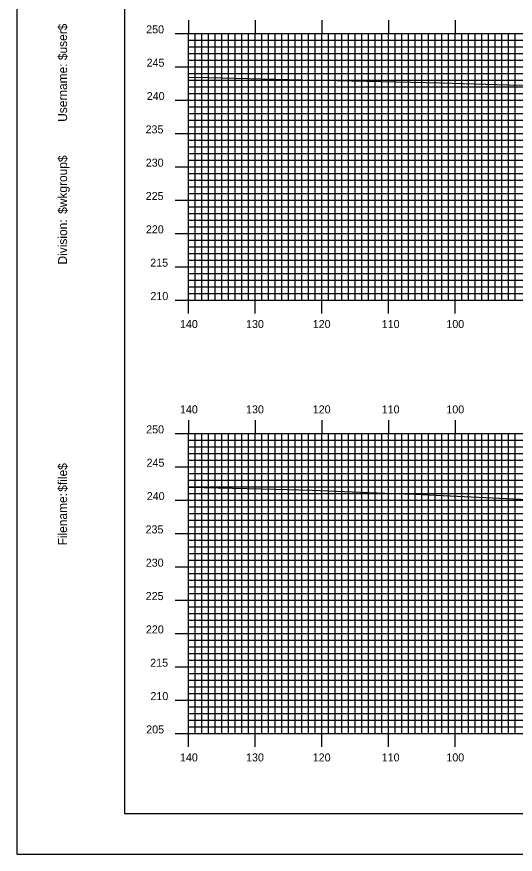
# Model space of a CAD drawing. Extents: x 1816489 to 1816833, y 442591 to 442811.
# Drawn here: x 1816489.3 to 1816564.1, y 442590.5 to 442716.2 of the extents above; entities that cross this region are included whole.
import ezdxf

# ---------------------------------------------------------------- set-up
doc = ezdxf.new("R2010")
doc.units = 0
for name, color, linetype in [('BORDER', 7, 'Continuous'), ('H_V ANNOTATION', 7, 'Continuous'), ('MAJOR', 7, 'Continuous'), ('MINOR', 7, 'Continuous'), ('PLOT BOUNDARY', 7, 'Continuous'), ('S_Roadway_Centerline', 7, 'Continuous')]:
    doc.layers.add(name, color=color, linetype=linetype)

msp = doc.modelspace()

# ---------------------------------------------------------------- linework, layer by layer
at = {"layer": 'BORDER'}
msp.add_lwpolyline([(1816505.47, 442596.67), (1816825.47, 442596.67), (1816825.47, 442806.67), (1816505.47, 442806.67)], close=True, dxfattribs=at)
at = {"layer": 'MAJOR'}
for p, q in [((1816515.07, 442715.67), (1816515.07, 442713.67)), ((1816525.07, 442715.67), (1816525.07, 442713.67)), ((1816535.07, 442715.67), (1816535.07, 442713.67)), ((1816545.07, 442715.67), (1816545.07, 442713.67)), ((1816555.07, 442715.67), (1816555.07, 442713.67)), ((1816513.07, 442713.67), (1816515.07, 442713.67)), ((1816515.07, 442713.67), (1816795.07, 442713.67)), ((1816515.07, 442673.67), (1816515.07, 442713.67)), ((1816515.07, 442673.67), (1816515.07, 442713.67)), ((1816515.07, 442713.67), (1816795.07, 442713.67)), ((1816525.07, 442673.67), (1816525.07, 442713.67)), ((1816535.07, 442673.67), (1816535.07, 442713.67)), ((1816545.07, 442673.67), (1816545.07, 442713.67)), ((1816555.07, 442673.67), (1816555.07, 442713.67)), ((1816513.07, 442708.67), (1816515.07, 442708.67)), ((1816515.07, 442708.67), (1816795.07, 442708.67)), ((1816513.07, 442703.67), (1816515.07, 442703.67)), ((1816515.07, 442703.67), (1816795.07, 442703.67)), ((1816513.07, 442698.67), (1816515.07, 442698.67)), ((1816515.07, 442698.67), (1816795.07, 442698.67)), ((1816513.07, 442693.67), (1816515.07, 442693.67)), ((1816515.07, 442693.67), (1816795.07, 442693.67)), ((1816513.07, 442688.67), (1816515.07, 442688.67)), ((1816515.07, 442688.67), (1816795.07, 442688.67)), ((1816513.07, 442683.67), (1816515.07, 442683.67)), ((1816515.07, 442683.67), (1816795.07, 442683.67)), ((1816513.07, 442678.67), (1816515.07, 442678.67)), ((1816515.07, 442678.67), (1816795.07, 442678.67)), ((1816513.07, 442673.67), (1816515.07, 442673.67)), ((1816515.07, 442673.67), (1816795.07, 442673.67)), ((1816515.07, 442673.67), (1816795.07, 442673.67)), ((1816515.07, 442671.66), (1816515.07, 442673.67)), ((1816525.07, 442671.66), (1816525.07, 442673.67)), ((1816535.07, 442671.66), (1816535.07, 442673.67)), ((1816545.07, 442671.66), (1816545.07, 442673.67)), ((1816555.07, 442671.66), (1816555.07, 442673.67)), ((1816515.07, 442655.67), (1816515.07, 442653.67)), ((1816525.07, 442655.67), (1816525.07, 442653.67)), ((1816535.07, 442655.67), (1816535.07, 442653.67)), ((1816545.07, 442655.67), (1816545.07, 442653.67)), ((1816555.07, 442655.67), (1816555.07, 442653.67)), ((1816513.07, 442653.67), (1816515.07, 442653.67)), ((1816515.07, 442653.67), (1816795.07, 442653.67)), ((1816515.07, 442608.67), (1816515.07, 442653.67)), ((1816515.07, 442608.67), (1816515.07, 442653.67)), ((1816515.07, 442653.67), (1816795.07, 442653.67)), ((1816525.07, 442608.67), (1816525.07, 442653.67)), ((1816535.07, 442608.67), (1816535.07, 442653.67)), ((1816545.07, 442608.67), (1816545.07, 442653.67)), ((1816555.07, 442608.67), (1816555.07, 442653.67)), ((1816513.07, 442648.67), (1816515.07, 442648.67)), ((1816515.07, 442648.67), (1816795.07, 442648.67)), ((1816513.07, 442643.67), (1816515.07, 442643.67)), ((1816515.07, 442643.67), (1816795.07, 442643.67)), ((1816513.07, 442638.67), (1816515.07, 442638.67)), ((1816515.07, 442638.67), (1816795.07, 442638.67)), ((1816513.07, 442633.67), (1816515.07, 442633.67)), ((1816515.07, 442633.67), (1816795.07, 442633.67)), ((1816513.07, 442628.67), (1816515.07, 442628.67)), ((1816515.07, 442628.67), (1816795.07, 442628.67)), ((1816513.07, 442623.67), (1816515.07, 442623.67)), ((1816515.07, 442623.67), (1816795.07, 442623.67)), ((1816513.07, 442618.67), (1816515.07, 442618.67)), ((1816515.07, 442618.67), (1816795.07, 442618.67)), ((1816513.07, 442613.67), (1816515.07, 442613.67)), ((1816515.07, 442613.67), (1816795.07, 442613.67)), ((1816513.07, 442608.67), (1816515.07, 442608.67)), ((1816515.07, 442608.67), (1816795.07, 442608.67)), ((1816515.07, 442608.67), (1816795.07, 442608.67)), ((1816515.07, 442606.66), (1816515.07, 442608.67)), ((1816525.07, 442606.66), (1816525.07, 442608.67)), ((1816535.07, 442606.66), (1816535.07, 442608.67)), ((1816545.07, 442606.66), (1816545.07, 442608.67)), ((1816555.07, 442606.66), (1816555.07, 442608.67))]:
    msp.add_line(p, q, dxfattribs=at)
at = {"layer": 'MINOR'}
for p, q in [((1816516.07, 442673.67), (1816516.07, 442713.67)), ((1816517.07, 442673.67), (1816517.07, 442713.67)), ((1816518.07, 442673.67), (1816518.07, 442713.67)), ((1816519.07, 442673.67), (1816519.07, 442713.67)), ((1816520.07, 442673.67), (1816520.07, 442713.67)), ((1816521.07, 442673.67), (1816521.07, 442713.67)), ((1816522.07, 442673.67), (1816522.07, 442713.67)), ((1816523.07, 442673.67), (1816523.07, 442713.67)), ((1816524.07, 442673.67), (1816524.07, 442713.67)), ((1816526.07, 442673.67), (1816526.07, 442713.67)), ((1816527.07, 442673.67), (1816527.07, 442713.67)), ((1816528.07, 442673.67), (1816528.07, 442713.67)), ((1816529.07, 442673.67), (1816529.07, 442713.67)), ((1816530.07, 442673.67), (1816530.07, 442713.67)), ((1816531.07, 442673.67), (1816531.07, 442713.67)), ((1816532.07, 442673.67), (1816532.07, 442713.67)), ((1816533.07, 442673.67), (1816533.07, 442713.67)), ((1816534.07, 442673.67), (1816534.07, 442713.67)), ((1816536.07, 442673.67), (1816536.07, 442713.67)), ((1816537.07, 442673.67), (1816537.07, 442713.67)), ((1816538.07, 442673.67), (1816538.07, 442713.67)), ((1816539.07, 442673.67), (1816539.07, 442713.67)), ((1816540.07, 442673.67), (1816540.07, 442713.67)), ((1816541.07, 442673.67), (1816541.07, 442713.67)), ((1816542.07, 442673.67), (1816542.07, 442713.67)), ((1816543.07, 442673.67), (1816543.07, 442713.67)), ((1816544.07, 442673.67), (1816544.07, 442713.67)), ((1816546.07, 442673.67), (1816546.07, 442713.67)), ((1816547.07, 442673.67), (1816547.07, 442713.67)), ((1816548.07, 442673.67), (1816548.07, 442713.67)), ((1816549.07, 442673.67), (1816549.07, 442713.67)), ((1816550.07, 442673.67), (1816550.07, 442713.67)), ((1816551.07, 442673.67), (1816551.07, 442713.67)), ((1816552.07, 442673.67), (1816552.07, 442713.67)), ((1816553.07, 442673.67), (1816553.07, 442713.67)), ((1816554.07, 442673.67), (1816554.07, 442713.67)), ((1816556.07, 442673.67), (1816556.07, 442713.67)), ((1816557.07, 442673.67), (1816557.07, 442713.67)), ((1816558.07, 442673.67), (1816558.07, 442713.67)), ((1816559.07, 442673.67), (1816559.07, 442713.67)), ((1816560.07, 442673.67), (1816560.07, 442713.67)), ((1816561.07, 442673.67), (1816561.07, 442713.67)), ((1816562.07, 442673.67), (1816562.07, 442713.67)), ((1816563.07, 442673.67), (1816563.07, 442713.67)), ((1816564.07, 442673.67), (1816564.07, 442713.67)), ((1816515.07, 442712.67), (1816795.07, 442712.67)), ((1816515.07, 442712.67), (1816517.08, 442712.67)), ((1816515.07, 442711.67), (1816795.07, 442711.67)), ((1816515.07, 442711.67), (1816517.08, 442711.67)), ((1816515.07, 442710.67), (1816795.07, 442710.67)), ((1816515.07, 442710.67), (1816517.08, 442710.67)), ((1816515.07, 442709.67), (1816795.07, 442709.67)), ((1816515.07, 442709.67), (1816517.08, 442709.67)), ((1816515.07, 442707.67), (1816795.07, 442707.67)), ((1816515.07, 442707.67), (1816517.08, 442707.67)), ((1816515.07, 442706.67), (1816795.07, 442706.67)), ((1816515.07, 442706.67), (1816517.08, 442706.67)), ((1816515.07, 442705.67), (1816795.07, 442705.67)), ((1816515.07, 442705.67), (1816517.08, 442705.67)), ((1816515.07, 442704.67), (1816795.07, 442704.67)), ((1816515.07, 442704.67), (1816517.08, 442704.67)), ((1816515.07, 442702.67), (1816795.07, 442702.67)), ((1816515.07, 442702.67), (1816517.08, 442702.67)), ((1816515.07, 442701.67), (1816795.07, 442701.67)), ((1816515.07, 442701.67), (1816517.08, 442701.67)), ((1816515.07, 442700.67), (1816795.07, 442700.67)), ((1816515.07, 442700.67), (1816517.08, 442700.67)), ((1816515.07, 442699.67), (1816795.07, 442699.67)), ((1816515.07, 442699.67), (1816517.08, 442699.67)), ((1816515.07, 442697.67), (1816795.07, 442697.67)), ((1816515.07, 442697.67), (1816517.08, 442697.67)), ((1816515.07, 442696.67), (1816795.07, 442696.67)), ((1816515.07, 442696.67), (1816517.08, 442696.67)), ((1816515.07, 442695.67), (1816795.07, 442695.67)), ((1816515.07, 442695.67), (1816517.08, 442695.67)), ((1816515.07, 442694.67), (1816795.07, 442694.67)), ((1816515.07, 442694.67), (1816517.08, 442694.67)), ((1816515.07, 442692.67), (1816795.07, 442692.67)), ((1816515.07, 442692.67), (1816517.08, 442692.67)), ((1816515.07, 442691.67), (1816795.07, 442691.67)), ((1816515.07, 442691.67), (1816517.08, 442691.67)), ((1816515.07, 442690.67), (1816795.07, 442690.67)), ((1816515.07, 442690.67), (1816517.08, 442690.67)), ((1816515.07, 442689.67), (1816795.07, 442689.67)), ((1816515.07, 442689.67), (1816517.08, 442689.67)), ((1816515.07, 442687.67), (1816795.07, 442687.67)), ((1816515.07, 442687.67), (1816517.08, 442687.67)), ((1816515.07, 442686.67), (1816795.07, 442686.67)), ((1816515.07, 442686.67), (1816517.08, 442686.67)), ((1816515.07, 442685.67), (1816795.07, 442685.67)), ((1816515.07, 442685.67), (1816517.08, 442685.67)), ((1816515.07, 442684.67), (1816795.07, 442684.67)), ((1816515.07, 442684.67), (1816517.08, 442684.67)), ((1816515.07, 442682.67), (1816795.07, 442682.67)), ((1816515.07, 442682.67), (1816517.08, 442682.67)), ((1816515.07, 442681.67), (1816795.07, 442681.67)), ((1816515.07, 442681.67), (1816517.08, 442681.67)), ((1816515.07, 442680.67), (1816795.07, 442680.67)), ((1816515.07, 442680.67), (1816517.08, 442680.67)), ((1816515.07, 442679.67), (1816795.07, 442679.67)), ((1816515.07, 442679.67), (1816517.08, 442679.67)), ((1816515.07, 442677.67), (1816795.07, 442677.67)), ((1816515.07, 442677.67), (1816517.08, 442677.67)), ((1816515.07, 442676.67), (1816795.07, 442676.67)), ((1816515.07, 442676.67), (1816517.08, 442676.67)), ((1816515.07, 442675.67), (1816795.07, 442675.67)), ((1816515.07, 442675.67), (1816517.08, 442675.67)), ((1816515.07, 442674.67), (1816795.07, 442674.67)), ((1816515.07, 442674.67), (1816517.08, 442674.67)), ((1816516.07, 442608.67), (1816516.07, 442653.67)), ((1816517.07, 442608.67), (1816517.07, 442653.67)), ((1816518.07, 442608.67), (1816518.07, 442653.67)), ((1816519.07, 442608.67), (1816519.07, 442653.67)), ((1816520.07, 442608.67), (1816520.07, 442653.67)), ((1816521.07, 442608.67), (1816521.07, 442653.67)), ((1816522.07, 442608.67), (1816522.07, 442653.67)), ((1816523.07, 442608.67), (1816523.07, 442653.67)), ((1816524.07, 442608.67), (1816524.07, 442653.67)), ((1816526.07, 442608.67), (1816526.07, 442653.67)), ((1816527.07, 442608.67), (1816527.07, 442653.67)), ((1816528.07, 442608.67), (1816528.07, 442653.67)), ((1816529.07, 442608.67), (1816529.07, 442653.67)), ((1816530.07, 442608.67), (1816530.07, 442653.67)), ((1816531.07, 442608.67), (1816531.07, 442653.67)), ((1816532.07, 442608.67), (1816532.07, 442653.67)), ((1816533.07, 442608.67), (1816533.07, 442653.67)), ((1816534.07, 442608.67), (1816534.07, 442653.67)), ((1816536.07, 442608.67), (1816536.07, 442653.67)), ((1816537.07, 442608.67), (1816537.07, 442653.67)), ((1816538.07, 442608.67), (1816538.07, 442653.67)), ((1816539.07, 442608.67), (1816539.07, 442653.67)), ((1816540.07, 442608.67), (1816540.07, 442653.67)), ((1816541.07, 442608.67), (1816541.07, 442653.67)), ((1816542.07, 442608.67), (1816542.07, 442653.67)), ((1816543.07, 442608.67), (1816543.07, 442653.67)), ((1816544.07, 442608.67), (1816544.07, 442653.67)), ((1816546.07, 442608.67), (1816546.07, 442653.67)), ((1816547.07, 442608.67), (1816547.07, 442653.67)), ((1816548.07, 442608.67), (1816548.07, 442653.67)), ((1816549.07, 442608.67), (1816549.07, 442653.67)), ((1816550.07, 442608.67), (1816550.07, 442653.67)), ((1816551.07, 442608.67), (1816551.07, 442653.67)), ((1816552.07, 442608.67), (1816552.07, 442653.67)), ((1816553.07, 442608.67), (1816553.07, 442653.67)), ((1816554.07, 442608.67), (1816554.07, 442653.67)), ((1816556.07, 442608.67), (1816556.07, 442653.67)), ((1816557.07, 442608.67), (1816557.07, 442653.67)), ((1816558.07, 442608.67), (1816558.07, 442653.67)), ((1816559.07, 442608.67), (1816559.07, 442653.67)), ((1816560.07, 442608.67), (1816560.07, 442653.67)), ((1816561.07, 442608.67), (1816561.07, 442653.67)), ((1816562.07, 442608.67), (1816562.07, 442653.67)), ((1816563.07, 442608.67), (1816563.07, 442653.67)), ((1816564.07, 442608.67), (1816564.07, 442653.67)), ((1816515.07, 442652.67), (1816795.07, 442652.67)), ((1816515.07, 442652.67), (1816517.08, 442652.67)), ((1816515.07, 442651.67), (1816795.07, 442651.67)), ((1816515.07, 442651.67), (1816517.08, 442651.67)), ((1816515.07, 442650.67), (1816795.07, 442650.67)), ((1816515.07, 442650.67), (1816517.08, 442650.67)), ((1816515.07, 442649.67), (1816795.07, 442649.67)), ((1816515.07, 442649.67), (1816517.08, 442649.67)), ((1816515.07, 442647.67), (1816795.07, 442647.67)), ((1816515.07, 442647.67), (1816517.08, 442647.67)), ((1816515.07, 442646.67), (1816795.07, 442646.67)), ((1816515.07, 442646.67), (1816517.08, 442646.67)), ((1816515.07, 442645.67), (1816795.07, 442645.67)), ((1816515.07, 442645.67), (1816517.08, 442645.67)), ((1816515.07, 442644.67), (1816795.07, 442644.67)), ((1816515.07, 442644.67), (1816517.08, 442644.67)), ((1816515.07, 442642.67), (1816795.07, 442642.67)), ((1816515.07, 442642.67), (1816517.08, 442642.67)), ((1816515.07, 442641.67), (1816795.07, 442641.67)), ((1816515.07, 442641.67), (1816517.08, 442641.67)), ((1816515.07, 442640.67), (1816795.07, 442640.67)), ((1816515.07, 442640.67), (1816517.08, 442640.67)), ((1816515.07, 442639.67), (1816795.07, 442639.67)), ((1816515.07, 442639.67), (1816517.08, 442639.67)), ((1816515.07, 442637.67), (1816795.07, 442637.67)), ((1816515.07, 442637.67), (1816517.08, 442637.67)), ((1816515.07, 442636.67), (1816795.07, 442636.67)), ((1816515.07, 442636.67), (1816517.08, 442636.67)), ((1816515.07, 442635.67), (1816795.07, 442635.67)), ((1816515.07, 442635.67), (1816517.08, 442635.67)), ((1816515.07, 442634.67), (1816795.07, 442634.67)), ((1816515.07, 442634.67), (1816517.08, 442634.67)), ((1816515.07, 442632.67), (1816795.07, 442632.67)), ((1816515.07, 442632.67), (1816517.08, 442632.67)), ((1816515.07, 442631.67), (1816795.07, 442631.67)), ((1816515.07, 442631.67), (1816517.08, 442631.67)), ((1816515.07, 442630.67), (1816795.07, 442630.67)), ((1816515.07, 442630.67), (1816517.08, 442630.67)), ((1816515.07, 442629.67), (1816795.07, 442629.67)), ((1816515.07, 442629.67), (1816517.08, 442629.67)), ((1816515.07, 442627.67), (1816795.07, 442627.67)), ((1816515.07, 442627.67), (1816517.08, 442627.67)), ((1816515.07, 442626.67), (1816795.07, 442626.67)), ((1816515.07, 442626.67), (1816517.08, 442626.67)), ((1816515.07, 442625.67), (1816795.07, 442625.67)), ((1816515.07, 442625.67), (1816517.08, 442625.67)), ((1816515.07, 442624.67), (1816795.07, 442624.67)), ((1816515.07, 442624.67), (1816517.08, 442624.67)), ((1816515.07, 442622.67), (1816795.07, 442622.67)), ((1816515.07, 442622.67), (1816517.08, 442622.67)), ((1816515.07, 442621.67), (1816795.07, 442621.67)), ((1816515.07, 442621.67), (1816517.08, 442621.67)), ((1816515.07, 442620.67), (1816795.07, 442620.67)), ((1816515.07, 442620.67), (1816517.08, 442620.67)), ((1816515.07, 442619.67), (1816795.07, 442619.67)), ((1816515.07, 442619.67), (1816517.08, 442619.67)), ((1816515.07, 442617.67), (1816795.07, 442617.67)), ((1816515.07, 442617.67), (1816517.08, 442617.67)), ((1816515.07, 442616.67), (1816795.07, 442616.67)), ((1816515.07, 442616.67), (1816517.08, 442616.67)), ((1816515.07, 442615.67), (1816795.07, 442615.67)), ((1816515.07, 442615.67), (1816517.08, 442615.67)), ((1816515.07, 442614.67), (1816795.07, 442614.67)), ((1816515.07, 442614.67), (1816517.08, 442614.67)), ((1816515.07, 442612.67), (1816795.07, 442612.67)), ((1816515.07, 442612.67), (1816517.08, 442612.67)), ((1816515.07, 442611.67), (1816795.07, 442611.67)), ((1816515.07, 442611.67), (1816517.08, 442611.67)), ((1816515.07, 442610.67), (1816795.07, 442610.67)), ((1816515.07, 442610.67), (1816517.08, 442610.67)), ((1816515.07, 442609.67), (1816795.07, 442609.67)), ((1816515.07, 442609.67), (1816517.08, 442609.67))]:
    msp.add_line(p, q, dxfattribs=at)
at = {"layer": 'PLOT BOUNDARY'}
msp.add_lwpolyline([(1816489.29, 442590.55), (1816829.29, 442590.55), (1816829.29, 442810.55), (1816489.29, 442810.55)], close=True, dxfattribs=at)
at = {"layer": 'S_Roadway_Centerline'}
for points in [[(1816515.07, 442707.12), (1816518.07, 442707.07), (1816534.11, 442706.67), (1816534.8, 442706.64), (1816535.11, 442706.64), (1816552.94, 442706.26), (1816563.02, 442705.93), (1816568.85, 442705.86), (1816578.69, 442705.68), (1816585.91, 442705.77), (1816602.93, 442704.98), (1816603.04, 442704.97), (1816603.11, 442704.97), (1816603.35, 442704.96), (1816630.05, 442703.98), (1816637.06, 442703.54), (1816643.69, 442703.48), (1816654.89, 442702.57), (1816658.1, 442702.19), (1816668.23, 442701.75), (1816671.11, 442701.59), (1816672.06, 442701.54), (1816678.58, 442701.01), (1816690.94, 442700.24)], [(1816515.07, 442645.59), (1816515.2, 442645.59), (1816528.13, 442645.3), (1816531.63, 442645.19), (1816533.62, 442645.16), (1816544.51, 442644.71), (1816547.47, 442644.6), (1816548.11, 442644.58), (1816549.05, 442644.54), (1816573.39, 442643.39)]]:
    msp.add_lwpolyline(points, dxfattribs=at)

# ---------------------------------------------------------------- texts
at = {"layer": 'BORDER'}
for s, p in [('$user$', (1816496.84, 442709.65)), ('Username:', (1816496.84, 442700.4)), ('$wkgroup$', (1816496.84, 442686.6)), ('Division:', (1816496.84, 442679)), ('$file$', (1816496.84, 442644.92)), ('Filename:', (1816496.84, 442636.86))]:
    msp.add_text(s, height=1.339, rotation=90, dxfattribs=at).set_placement(p)
at = {"layer": 'H_V ANNOTATION'}
for s, p in [('250', (1816508.71, 442713.67)), ('245', (1816508.77, 442708.67)), ('240', (1816508.8, 442703.67)), ('235', (1816508.62, 442698.67)), ('230', (1816508.65, 442693.67)), ('225', (1816508.64, 442688.67)), ('220', (1816508.67, 442683.67)), ('215', (1816509.32, 442678.67)), ('210', (1816509.35, 442673.67)), ('140', (1816513.78, 442669.47)), ('130', (1816523.7, 442669.47)), ('120', (1816533.71, 442669.47)), ('110', (1816544.06, 442669.47)), ('100', (1816553.76, 442669.47)), ('140', (1816513.78, 442656.67)), ('130', (1816523.7, 442656.67)), ('120', (1816533.71, 442656.67)), ('110', (1816544.06, 442656.67)), ('100', (1816553.76, 442656.67)), ('250', (1816508.71, 442653.67)), ('245', (1816508.77, 442648.67)), ('240', (1816508.8, 442643.67)), ('235', (1816508.62, 442638.67)), ('230', (1816508.65, 442633.67)), ('225', (1816508.64, 442628.67)), ('220', (1816508.67, 442623.67)), ('215', (1816509.32, 442618.67)), ('210', (1816509.35, 442613.67)), ('205', (1816508.72, 442608.67)), ('140', (1816513.78, 442604.47)), ('130', (1816523.7, 442604.47)), ('120', (1816533.71, 442604.47)), ('110', (1816544.06, 442604.47)), ('100', (1816553.76, 442604.47))]:
    msp.add_text(s, height=1.2, dxfattribs=at).set_placement(p)
at = {"layer": 'MAJOR'}
for p in [(1816515.06, 442673.67), (1816515.06, 442608.67)]:
    msp.add_text('-', height=0.012, dxfattribs=at).set_placement(p)

doc.saveas('drawing.dxf')
